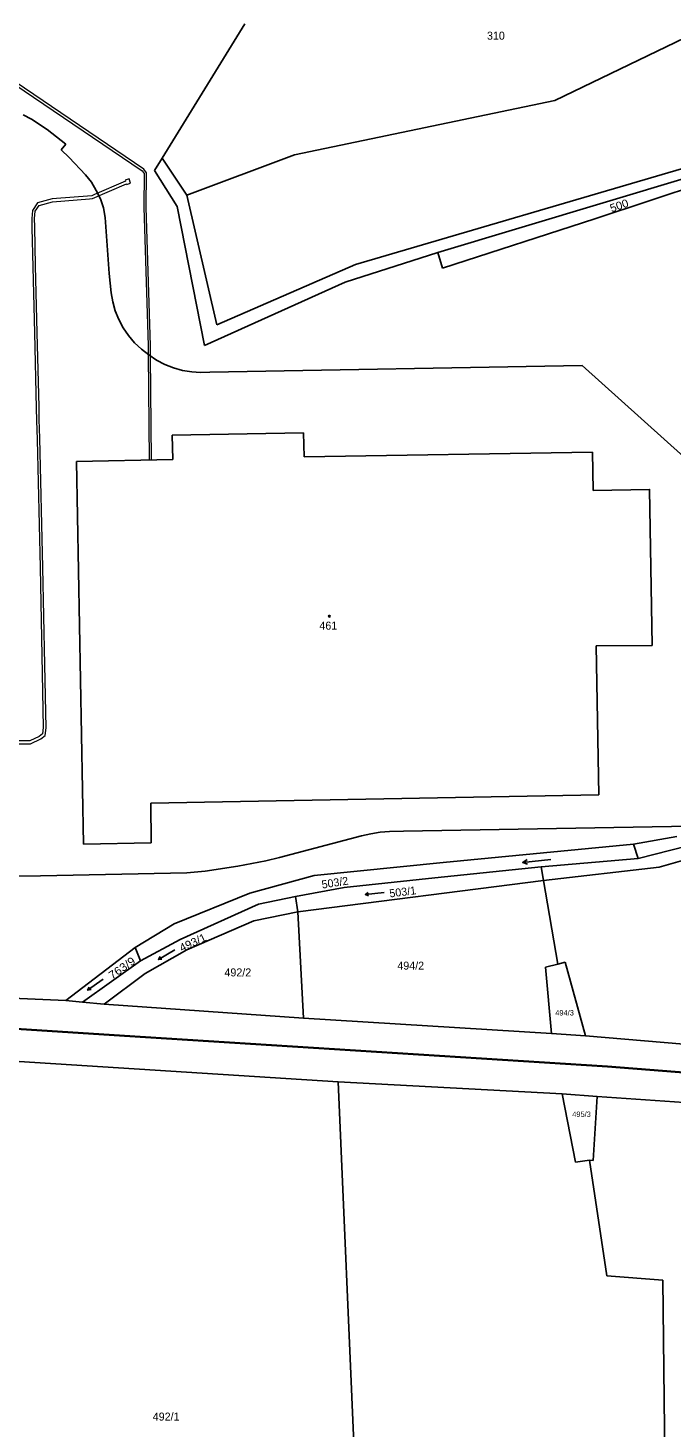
# Model space of a CAD drawing. Extents: x -701211 to -698780, y -1014269 to -1012378.
# Drawn here: x -699751 to -699614.3, y -1013104.1 to -1012806.8 of the extents above; entities that cross this region are included whole.
import ezdxf
from ezdxf.enums import TextEntityAlignment as Align

# ---------------------------------------------------------------- set-up
doc = ezdxf.new("R2010")
doc.units = 0
doc.header["$LTSCALE"] = 0.68
for name, color, linetype, lineweight in [('1', 7, 'Continuous', 25), ('13', 7, 'Continuous', 13), ('3', 7, 'Continuous', 25), ('5', 7, 'Continuous', 25), ('6', 7, 'Continuous', 35)]:
    doc.layers.add(name, color=color, linetype=linetype, lineweight=lineweight)
doc.layers.add('2', color=7, linetype='Continuous')

msp = doc.modelspace()

# ---------------------------------------------------------------- linework, layer by layer
at = {"layer": '1'}
for p, q in [((-699579.58, -1012793.42), (-699639.24, -1012822.29)), ((-699704.98, -1012806), (-699722.55, -1012834.53)), ((-699639.24, -1012822.29), (-699694.5, -1012833.83)), ((-699752.05, -1012825.28), (-699750.29, -1012826.23)), ((-699750.29, -1012826.23), (-699746.94, -1012828.4)), ((-699746.94, -1012828.4), (-699743, -1012831.52)), ((-699743, -1012831.52), (-699743.99, -1012832.75)), ((-699743.99, -1012832.75), (-699742.27, -1012834.37)), ((-699742.27, -1012834.37), (-699738.84, -1012838.03)), ((-699722.55, -1012834.53), (-699724.18, -1012837.16)), ((-699717.3, -1012842.36), (-699722.55, -1012834.53)), ((-699694.5, -1012833.83), (-699717.3, -1012842.36)), ((-699738.84, -1012838.03), (-699737.56, -1012839.63)), ((-699719.37, -1012844.74), (-699724.18, -1012837.16)), ((-699681.49, -1012857.08), (-699611.11, -1012836.43)), ((-699737.56, -1012839.63), (-699736.56, -1012841.38)), ((-699664.08, -1012854.54), (-699611.06, -1012838.62)), ((-699607.36, -1012839.61), (-699630.7, -1012847.42)), ((-699736.56, -1012841.38), (-699735.67, -1012843.15)), ((-699735.67, -1012843.15), (-699734.98, -1012845.08)), ((-699717.3, -1012842.36), (-699710.94, -1012869.92)), ((-699734.98, -1012845.08), (-699734.67, -1012847.08)), ((-699734.67, -1012847.08), (-699733.79, -1012859.03)), ((-699713.54, -1012874.28), (-699719.37, -1012844.74)), ((-699630.7, -1012847.42), (-699663.03, -1012857.87)), ((-699664.08, -1012854.54), (-699683.73, -1012860.83)), ((-699663.03, -1012857.87), (-699664.08, -1012854.54)), ((-699710.94, -1012869.92), (-699681.49, -1012857.08)), ((-699733.79, -1012859.03), (-699733.42, -1012863.08)), ((-699683.73, -1012860.83), (-699713.54, -1012874.28)), ((-699733.42, -1012863.08), (-699733.05, -1012865.02)), ((-699733.05, -1012865.02), (-699732.53, -1012866.96)), ((-699732.53, -1012866.96), (-699731.75, -1012868.78)), ((-699731.75, -1012868.78), (-699730.85, -1012870.54)), ((-699730.85, -1012870.54), (-699729.72, -1012872.19)), ((-699729.72, -1012872.19), (-699728.43, -1012873.74)), ((-699728.43, -1012873.74), (-699726.98, -1012875.1)), ((-699726.98, -1012875.1), (-699725.39, -1012876.29)), ((-699725.39, -1012876.29), (-699723.77, -1012877.4)), ((-699723.77, -1012877.4), (-699721.98, -1012878.33)), ((-699721.98, -1012878.33), (-699720.14, -1012879.08)), ((-699720.14, -1012879.08), (-699718.24, -1012879.6)), ((-699718.24, -1012879.6), (-699716.23, -1012879.93)), ((-699712.42, -1012879.96), (-699633.39, -1012878.56)), ((-699633.39, -1012878.56), (-699594.25, -1012913.85)), ((-699716.23, -1012879.93), (-699714.4, -1012880.03)), ((-699714.4, -1012880.03), (-699712.42, -1012879.96)), ((-699720.42, -1012893.34), (-699692.59, -1012892.83)), ((-699720.32, -1012898.49), (-699720.42, -1012893.34)), ((-699692.59, -1012892.83), (-699692.45, -1012897.97)), ((-699692.45, -1012897.97), (-699631.19, -1012896.95)), ((-699631.19, -1012896.95), (-699631.04, -1012905.13)), ((-699740.76, -1012898.98), (-699720.32, -1012898.49)), ((-699739.25, -1012980.26), (-699740.76, -1012898.98)), ((-699618.55, -1012938.03), (-699630.43, -1012938.13)), ((-699630.43, -1012938.13), (-699629.85, -1012969.75)), ((-699629.85, -1012969.75), (-699724.99, -1012971.5)), ((-699724.99, -1012971.5), (-699724.87, -1012979.98)), ((-699676.3, -1012977.71), (-699678.3, -1012978.04)), ((-699674.33, -1012977.55), (-699676.3, -1012977.71)), ((-699724.87, -1012979.98), (-699739.25, -1012980.26)), ((-699680.23, -1012978.47), (-699697.65, -1012983.04)), ((-699678.3, -1012978.04), (-699680.23, -1012978.47)), ((-699662.91, -1012984.12), (-699622.53, -1012980.26)), ((-699622.53, -1012980.26), (-699613.28, -1012978.64)), ((-699621.55, -1012983.3), (-699622.53, -1012980.26)), ((-699621.55, -1012983.3), (-699602.03, -1012978.27)), ((-699617.05, -1012985.11), (-699596.5, -1012979.28)), ((-699700.57, -1012983.75), (-699706.5, -1012984.88)), ((-699697.65, -1012983.04), (-699700.57, -1012983.75)), ((-699642.1, -1012985.09), (-699621.55, -1012983.3)), ((-699717.36, -1012986.35), (-699748.37, -1012986.94)), ((-699713.44, -1012985.95), (-699717.36, -1012986.35)), ((-699706.5, -1012984.88), (-699713.44, -1012985.95)), ((-699690.28, -1012986.9), (-699662.91, -1012984.12)), ((-699664.7, -1012987.41), (-699642.1, -1012985.09)), ((-699641.64, -1012987.99), (-699642.1, -1012985.09)), ((-699641.64, -1012987.99), (-699617.05, -1012985.11)), ((-699748.37, -1012986.94), (-699815.96, -1012988.25)), ((-699703.92, -1012990.67), (-699690.28, -1012986.9)), ((-699694.27, -1012991.36), (-699683.9, -1012989.48)), ((-699693.77, -1012994.62), (-699641.64, -1012987.99)), ((-699683.9, -1012989.48), (-699664.7, -1012987.41)), ((-699641.64, -1012987.99), (-699638.55, -1013005.7)), ((-699719.98, -1012997.14), (-699703.92, -1012990.67)), ((-699702.12, -1012992.98), (-699694.27, -1012991.36)), ((-699694.27, -1012991.36), (-699693.77, -1012994.62)), ((-699718.77, -1013000.52), (-699702.12, -1012992.98)), ((-699703.11, -1012996.51), (-699693.77, -1012994.62)), ((-699692.54, -1013017.23), (-699693.77, -1012994.62)), ((-699728.32, -1013002.16), (-699719.98, -1012997.14)), ((-699717.29, -1013002.7), (-699703.11, -1012996.51)), ((-699727.16, -1013005.05), (-699718.77, -1013000.52)), ((-699743.03, -1013013.45), (-699728.32, -1013002.16)), ((-699727.16, -1013005.05), (-699728.32, -1013002.16)), ((-699726.17, -1013007.73), (-699717.29, -1013002.7)), ((-699727.16, -1013005.05), (-699739.47, -1013013.78)), ((-699638.55, -1013005.7), (-699641.17, -1013006.38)), ((-699641.17, -1013006.38), (-699639.95, -1013020.43)), ((-699637.05, -1013005.31), (-699638.55, -1013005.7)), ((-699637.05, -1013005.31), (-699632.72, -1013020.93)), ((-699734.88, -1013014.21), (-699726.17, -1013007.73)), ((-699765.28, -1013012.51), (-699743.03, -1013013.45)), ((-699743.03, -1013013.45), (-699739.47, -1013013.78)), ((-699739.47, -1013013.78), (-699734.88, -1013014.21)), ((-699734.88, -1013014.21), (-699692.54, -1013017.23)), ((-699692.54, -1013017.23), (-699639.95, -1013020.43)), ((-699639.95, -1013020.43), (-699632.72, -1013020.93)), ((-699632.72, -1013020.93), (-699563.71, -1013026.94)), ((-699752.9, -1013026.43), (-699685.22, -1013030.72)), ((-699685.22, -1013030.72), (-699637.68, -1013033.25)), ((-699681.34, -1013119.14), (-699685.22, -1013030.72)), ((-699637.68, -1013033.25), (-699630.2, -1013033.84)), ((-699634.8, -1013047.77), (-699637.68, -1013033.25)), ((-699631.07, -1013047.46), (-699630.2, -1013033.84)), ((-699630.2, -1013033.84), (-699549.93, -1013039.34)), ((-699631.88, -1013047.37), (-699634.8, -1013047.77)), ((-699628.15, -1013071.91), (-699631.88, -1013047.37)), ((-699631.88, -1013047.37), (-699631.07, -1013047.46)), ((-699616.27, -1013072.85), (-699628.15, -1013071.91)), ((-699615.63, -1013132.71), (-699616.27, -1013072.85))]:
    msp.add_line(p, q, dxfattribs=at)
for points in [[(-699631.04, -1012905.13), (-699619.11, -1012904.89), (-699618.55, -1012938.03)], [(-699610.43, -1012976.41), (-699671.34, -1012977.47), (-699674.33, -1012977.55)]]:
    msp.add_lwpolyline(points, dxfattribs=at)
at = {"layer": '13'}
msp.add_lwpolyline([(-699726.46, -1012844.89), (-699726.24, -1012851.79), (-699725.54, -1012874.31), (-699725.52, -1012876.19), (-699725.33, -1012898.61), (-699724.83, -1012898.6), (-699725.02, -1012876.54), (-699725.04, -1012874.31), (-699725.74, -1012851.77), (-699725.96, -1012844.89), (-699725.87, -1012837.63), (-699726.46, -1012836.82), (-699753.79, -1012818.3), (-699773.9, -1012804.91), (-699793.15, -1012790.89), (-699795.55, -1012790.19), (-699795.69, -1012790.67), (-699793.37, -1012791.35), (-699774.18, -1012805.31), (-699754.07, -1012818.72), (-699726.82, -1012837.18), (-699726.37, -1012837.79)], close=True, dxfattribs=at)
msp.add_lwpolyline([(-699752.92, -1012958.92), (-699750.5, -1012958.89), (-699748.33, -1012957.87), (-699747.4, -1012957.14), (-699747.21, -1012955.53), (-699747.47, -1012942.15), (-699747.88, -1012921.48), (-699748.54, -1012894), (-699748.64, -1012889.99), (-699748.7, -1012887.35), (-699749.08, -1012871.6), (-699749.42, -1012857.37), (-699749.62, -1012849.09), (-699749.66, -1012847.31), (-699749.49, -1012845.8), (-699748.67, -1012844.54), (-699745.81, -1012843.78), (-699737.97, -1012843.12), (-699737.36, -1012843.06), (-699730.13, -1012839.99), (-699730.1, -1012840.09), (-699729.26, -1012839.81), (-699729.54, -1012838.88), (-699730.39, -1012839.19), (-699730.32, -1012839.42), (-699736.91, -1012842.22), (-699737.5, -1012842.48), (-699745.91, -1012843.18), (-699749.05, -1012844.02), (-699750.07, -1012845.6), (-699750.26, -1012847.29), (-699750.21, -1012849.34), (-699750.01, -1012857.63), (-699749.68, -1012871.62), (-699749.3, -1012887.62), (-699749.23, -1012890.26), (-699749.13, -1012894.28), (-699748.48, -1012921.5), (-699748.11, -1012940.23), (-699747.81, -1012955.49), (-699747.96, -1012956.82), (-699748.65, -1012957.35), (-699750.64, -1012958.29), (-699753.02, -1012958.32)], dxfattribs=at)
at = {"layer": '3'}
for p, q in [((-699646.032, -1012984.127), (-699645.112, -1012983.526)), ((-699679.421, -1012990.916), (-699678.805, -1012990.513)), ((-699723.374, -1013004.706), (-699722.975, -1013004.087)), ((-699738.379, -1013011.245), (-699738.036, -1013010.594))]:
    msp.add_line(p, q, dxfattribs=at)
for points in [[(-699640.064, -1012983.5), (-699646.032, -1012984.127), (-699645.007, -1012984.523)], [(-699675.423, -1012990.495), (-699679.421, -1012990.916), (-699678.735, -1012991.181)], [(-699719.892, -1013002.696), (-699723.374, -1013004.706), (-699722.639, -1013004.669)], [(-699735.086, -1013008.939), (-699738.379, -1013011.245), (-699737.65, -1013011.144)]]:
    msp.add_lwpolyline(points, dxfattribs=at)
at = {"layer": '5'}
msp.add_circle((-699687.0768, -1012931.8192), 0.175, dxfattribs=at)
at = {"layer": '6'}
for p, q in [((-699821.14, -1013015.19), (-699730.55, -1013020.93)), ((-699730.55, -1013020.93), (-699628, -1013027.5)), ((-699628, -1013027.5), (-699527.57, -1013035.36))]:
    msp.add_line(p, q, dxfattribs=at)

# ---------------------------------------------------------------- texts
at = {"layer": '2'}
for s, height, p in [('310', 1.7, (-699651.719, -1012809.335)), ('461', 1.7, (-699687.289, -1012934.665)), ('492/2', 1.7, (-699706.5, -1013008.335)), ('494/2', 1.7, (-699669.8, -1013006.895)), ('494/3', 1.14, (-699637.139, -1013016.635)), ('495/3', 1.14, (-699633.539, -1013038.185)), ('492/1', 1.7, (-699721.72, -1013102.695))]:
    msp.add_text(s, height=height, dxfattribs=at).set_placement(p, align=Align.CENTER)
for s, rotation, width, p in [('500', 19, 1.05, (-699625.2802, -1012845.3829)), ('493/1', 25, 1.05, (-699715.7067, -1013001.9191)), ('763/9', 35, 1.1, (-699730.6175, -1013007.2434))]:
    msp.add_text(s, height=1.7, rotation=rotation, dxfattribs=dict(at, width=width)).set_placement(p, align=Align.CENTER)
for s, rotation, p in [('503/2', 9, (-699685.755, -1012989.2386)), ('503/1', 7, (-699671.4051, -1012991.2149))]:
    msp.add_text(s, height=1.7, rotation=rotation, dxfattribs=at).set_placement(p, align=Align.CENTER)

doc.saveas('drawing.dxf')
